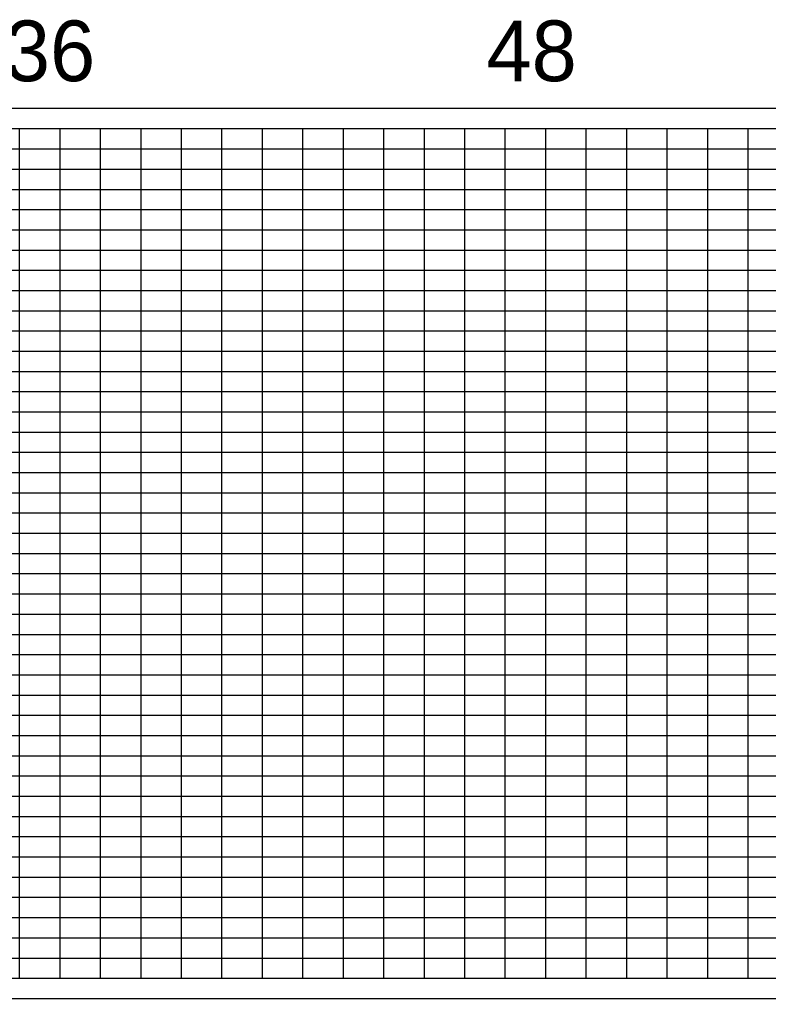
# Model space of a CAD drawing. Extents: x 1950433 to 1956806, y 750939 to 777666.
# Drawn here: x 1953126 to 1954051, y 758439 to 759649 of the extents above; entities that cross this region are included whole.
import ezdxf

# ---------------------------------------------------------------- set-up
doc = ezdxf.new("R2010")
doc.units = 0
doc.layers.add('RD_PD_WallFill', color=7, linetype='Continuous')
doc.layers.add('RD_SHT_IplotShp', color=7, linetype='Continuous')

msp = doc.modelspace()

# ---------------------------------------------------------------- linework, layer by layer
at = {"layer": 'RD_PD_WallFill'}
for p, q in [((1951376.4, 759514.1), (1956726.4, 759514.2)), ((1953126.4, 758464.1), (1953126.4, 759514.1)), ((1953176.4, 758464.1), (1953176.4, 759514.1)), ((1953226.4, 758464.1), (1953226.4, 759514.1)), ((1953276.4, 758464.1), (1953276.4, 759514.1)), ((1953326.4, 758464.1), (1953326.4, 759514.1)), ((1953376.4, 758464.1), (1953376.4, 759514.1)), ((1953426.4, 758464.1), (1953426.4, 759514.1)), ((1953476.4, 758464.1), (1953476.4, 759514.1)), ((1953526.4, 758464.1), (1953526.4, 759514.1)), ((1953576.4, 758464.1), (1953576.4, 759514.1)), ((1953626.4, 758464.1), (1953626.4, 759514.1)), ((1953676.4, 758464.1), (1953676.4, 759514.1)), ((1953726.4, 758464.1), (1953726.4, 759514.1)), ((1953776.4, 758464.1), (1953776.4, 759514.1)), ((1953826.4, 758464.1), (1953826.4, 759514.1)), ((1953876.4, 758464.1), (1953876.4, 759514.1)), ((1953926.4, 758464.1), (1953926.4, 759514.1)), ((1953976.4, 758464.1), (1953976.4, 759514.1)), ((1954026.4, 758464.1), (1954026.4, 759514.1)), ((1951826.4, 759489.1), (1956726.4, 759489.1)), ((1951826.4, 759464.1), (1956726.4, 759464.1)), ((1951826.4, 759439.1), (1956726.4, 759439.1)), ((1951826.4, 759414.2), (1956726.4, 759414.1)), ((1951826.4, 759389.1), (1956726.4, 759389.2)), ((1951376.4, 759364.1), (1956726.4, 759364.1)), ((1951376.4, 759339.1), (1956726.4, 759339.1)), ((1951376.4, 759314.1), (1956726.4, 759314.2)), ((1951376.4, 759289.2), (1956726.4, 759289.1)), ((1951376.4, 759264.2), (1956726.4, 759264.2)), ((1951376.4, 759239.1), (1956726.4, 759239.1)), ((1951376.4, 759214.1), (1956726.4, 759214.1)), ((1951376.4, 759189.2), (1956726.4, 759189.1)), ((1951376.4, 759164.1), (1956726.4, 759164.1)), ((1951376.4, 759139.2), (1956726.4, 759139.1)), ((1951376.4, 759114.1), (1956726.4, 759114.1)), ((1951376.4, 759089.1), (1956726.4, 759089.2)), ((1951376.4, 759064.1), (1956726.4, 759064.1)), ((1951376.4, 759039.1), (1956726.4, 759039.2)), ((1951376.4, 759014.1), (1956726.4, 759014.1)), ((1951376.4, 758989.1), (1956726.4, 758989.1)), ((1951376.4, 758964.2), (1956726.4, 758964.1)), ((1951376.4, 758939.1), (1956726.4, 758939.1)), ((1951376.4, 758914.1), (1956726.4, 758914.1)), ((1951376.4, 758889.1), (1956726.4, 758889.1)), ((1951376.4, 758864.1), (1956726.4, 758864.2)), ((1951376.4, 758839.1), (1956726.4, 758839.1)), ((1951376.4, 758814.1), (1956726.4, 758814.1)), ((1951376.4, 758789.1), (1956726.4, 758789.1)), ((1951376.4, 758764.1), (1956726.4, 758764.1)), ((1951376.4, 758739.1), (1956726.4, 758739.1)), ((1951376.4, 758714.1), (1956726.4, 758714.1)), ((1951376.4, 758689.1), (1956726.4, 758689.1)), ((1951376.4, 758664.1), (1956726.4, 758664.1)), ((1951376.4, 758639.1), (1956726.4, 758639.1)), ((1951376.4, 758614.1), (1956726.4, 758614.1)), ((1951376.4, 758589.1), (1956726.4, 758589.1)), ((1951376.4, 758564.1), (1956726.4, 758564.1)), ((1951376.4, 758539.1), (1956726.4, 758539.1)), ((1951376.4, 758514.1), (1956726.4, 758514.1)), ((1951426.4, 758489.1), (1956726.4, 758489.1)), ((1951376.4, 758464.1), (1956726.4, 758464.1))]:
    msp.add_line(p, q, dxfattribs=at)
at = {"layer": 'RD_SHT_IplotShp'}
msp.add_lwpolyline([(1951351.4, 758439.1), (1954951.4, 758439.1), (1954951.4, 759539.1), (1951351.4, 759539.1)], close=True, dxfattribs=at)

# ---------------------------------------------------------------- texts
at = {"layer": 'RD_PD_WallFill'}
for s, p in [('22x36', (1952946.5, 759572.8)), ('48', (1953703.1, 759572.8))]:
    msp.add_text(s, height=75, dxfattribs=at).set_placement(p)

doc.saveas('drawing.dxf')
